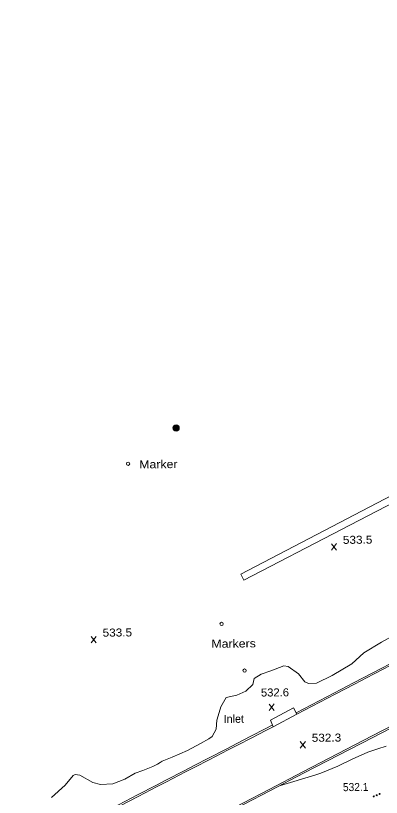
# Model space of a CAD drawing. Extents: x 2361284 to 2366480, y 6976556 to 6985346.
# Drawn here: x 2362327.9 to 2362547.3, y 6978202.6 to 6978671.2 of the extents above; entities that cross this region are included whole.
import ezdxf

# ---------------------------------------------------------------- set-up
doc = ezdxf.new("R2010")
doc.units = 0
doc.header["$LTSCALE"] = 1.9
for name, color, linetype, lineweight in [('12', 7, 'Continuous', 13), ('13', 7, 'Continuous', 13), ('21', 7, 'Continuous', 13), ('3', 7, 'Continuous', 13), ('4', 7, 'Continuous', 13), ('7', 7, 'Continuous', 13), ('8', 7, 'Continuous', 13)]:
    doc.layers.add(name, color=color, linetype=linetype, lineweight=lineweight)

msp = doc.modelspace()

# ---------------------------------------------------------------- linework, layer by layer
at = {"layer": '12'}
for p, q in [((2362520.443, 6978350.813), (2362517.326, 6978354.664)), ((2362517.363, 6978350.784), (2362520.406, 6978354.693)), ((2362376.315, 6978295.21), (2362373.198, 6978299.061)), ((2362373.235, 6978295.181), (2362376.278, 6978299.09)), ((2362483.024, 6978254.721), (2362479.907, 6978258.572)), ((2362479.944, 6978254.692), (2362482.987, 6978258.601)), ((2362501.75, 6978232.188), (2362498.633, 6978236.039)), ((2362498.67, 6978232.159), (2362501.713, 6978236.068))]:
    msp.add_line(p, q, dxfattribs=at)
at = {"layer": '13'}
for points in [[(2362606.115, 6978310.613), (2362602.962, 6978315.072), (2362600.891, 6978317.323), (2362599.072, 6978317.856), (2362595.125, 6978316.798), (2362585.879, 6978312.11), (2362580.474, 6978310.519), (2362568.627, 6978304.796), (2362556.059, 6978300.457), (2362547.294, 6978295.592), (2362536.815, 6978289.202), (2362529.547, 6978282.674), (2362517.762, 6978275.611), (2362508.376, 6978271.131), (2362503.665, 6978270.847), (2362501.428, 6978271.825), (2362497.551, 6978276.719), (2362491.32, 6978281.01)], [(2362491.32, 6978281.01), (2362488.805, 6978281.466), (2362481.064, 6978278.423), (2362475.303, 6978276.368), (2362470.937, 6978273.825), (2362470.151, 6978270.277), (2362465.908, 6978266.307), (2362460.671, 6978263.787), (2362454.283, 6978262.506), (2362451.028, 6978256.855), (2362450.531, 6978255.46), (2362448.674, 6978248.842), (2362448.255, 6978243.458), (2362445.722, 6978239.13), (2362443.76, 6978237.625), (2362438.794, 6978234.968), (2362430.964, 6978230.703), (2362421.833, 6978226.705), (2362415.755, 6978224.258)], [(2362550.136, 6978233.316), (2362545.21, 6978231.769), (2362539.25, 6978229.663), (2362529.831, 6978225.463), (2362521.169, 6978221.24), (2362511.088, 6978217.094), (2362507.351, 6978215.899), (2362486.807, 6978209.793)], [(2362415.755, 6978224.258), (2362414.542, 6978223.547), (2362412.942, 6978222.471), (2362410.174, 6978221.155), (2362404.136, 6978218.807), (2362399.702, 6978217.165), (2362393.435, 6978213.595), (2362386.182, 6978210.806), (2362378.866, 6978210.337), (2362374.135, 6978211.442), (2362366.501, 6978216.019), (2362363.638, 6978216.365), (2362362.343, 6978215.79), (2362357.738, 6978210.016), (2362349.417, 6978202.565)]]:
    msp.add_lwpolyline(points, dxfattribs=at)
at = {"layer": '21'}
for centre in [(2362546.243, 6978204.663), (2362542.717, 6978203.145), (2362544.486, 6978203.89)]:
    msp.add_circle(centre, 0.3, dxfattribs=at)
at = {"layer": '3'}
msp.add_line((2362482.302, 6978244.952), (2362496.631, 6978252.519), dxfattribs=at)
for points in [[(2362462.946, 6978336.358), (2362464.803, 6978332.781), (2362699.124, 6978454.268), (2362589.904, 6978664.638)], [(2362981.445, 6978467.35), (2362809.007, 6978377.835), (2362710.231, 6978326.575), (2362660.839, 6978300.953), (2362647.619, 6978294.102), (2362621.168, 6978280.42), (2362568.25, 6978253.087), (2362541.798, 6978239.407), (2362500.635, 6978218.082), (2362480.057, 6978207.412), (2362449.196, 6978191.397), (2362402.915, 6978167.353), (2362365.587, 6978147.925), (2362340.71, 6978134.956), (2362290.974, 6978108.986)], [(2362981.883, 6978466.494), (2362809.445, 6978376.979), (2362710.67, 6978325.719), (2362661.278, 6978300.097), (2362648.058, 6978293.246), (2362621.607, 6978279.564), (2362568.688, 6978252.231), (2362542.236, 6978238.551), (2362501.073, 6978217.226), (2362480.496, 6978206.556), (2362449.635, 6978190.541), (2362403.354, 6978166.498), (2362366.029, 6978147.073), (2362341.154, 6978134.106), (2362291.422, 6978108.14)], [(2362496.183, 6978253.375), (2362519.166, 6978265.37), (2362530.658, 6978271.366), (2362542.151, 6978277.359), (2362547.898, 6978280.355), (2362559.394, 6978286.344), (2362565.143, 6978289.337), (2362573.767, 6978293.825), (2362581.434, 6978297.812), (2362585.267, 6978299.805), (2362591.019, 6978302.793), (2362599.647, 6978307.272), (2362608.277, 6978311.748), (2362612.593, 6978313.984), (2362661.176, 6978339.151), (2362725.955, 6978372.706), (2362758.344, 6978389.485), (2362789.439, 6978405.594), (2362804.986, 6978413.649)], [(2362496.631, 6978252.519), (2362519.612, 6978264.514), (2362531.103, 6978270.509), (2362542.596, 6978276.503), (2362548.342, 6978279.499), (2362559.837, 6978285.488), (2362565.585, 6978288.481), (2362574.208, 6978292.969), (2362581.874, 6978296.956), (2362585.708, 6978298.949), (2362591.458, 6978301.937), (2362600.086, 6978306.416), (2362608.716, 6978310.892), (2362613.031, 6978313.128), (2362629.225, 6978321.518), (2362661.614, 6978338.296), (2362726.393, 6978371.85), (2362758.782, 6978388.629), (2362789.877, 6978404.739), (2362805.424, 6978412.794)], [(2362325.127, 6978164.622), (2362329.659, 6978166.981), (2362336.458, 6978170.519), (2362345.525, 6978175.235), (2362350.058, 6978177.591), (2362356.86, 6978181.125), (2362367.063, 6978186.423), (2362377.135, 6978191.649), (2362382.171, 6978194.261), (2362389.727, 6978198.179), (2362401.061, 6978204.052), (2362412.397, 6978209.922), (2362418.065, 6978212.856), (2362429.403, 6978218.722), (2362435.073, 6978221.653), (2362443.578, 6978226.049), (2362454.92, 6978231.908), (2362460.592, 6978234.836), (2362469.1, 6978239.226), (2362477.609, 6978243.614), (2362481.864, 6978245.808)], [(2362325.57, 6978163.766), (2362330.101, 6978166.126), (2362336.9, 6978169.664), (2362345.965, 6978174.379), (2362350.498, 6978176.736), (2362357.299, 6978180.27), (2362367.501, 6978185.568), (2362377.573, 6978190.795), (2362382.609, 6978193.407), (2362390.164, 6978197.324), (2362401.498, 6978203.198), (2362412.834, 6978209.068), (2362418.502, 6978212.002), (2362429.841, 6978217.867), (2362435.51, 6978220.799), (2362444.016, 6978225.194), (2362455.358, 6978231.052), (2362461.029, 6978233.98), (2362469.538, 6978238.37), (2362478.047, 6978242.759), (2362482.302, 6978244.952)]]:
    msp.add_lwpolyline(points, dxfattribs=at)
at = {"layer": '4'}
for centre, radius in [((2362424.197, 6978424.048), 1.9), ((2362424.197, 6978424.048), 1.442), ((2362424.197, 6978424.048), 0.539), ((2362424.197, 6978424.048), 0.192), ((2362395.411, 6978402.624), 1), ((2362451.468, 6978306.532), 1), ((2362465.245, 6978278.592), 1)]:
    msp.add_circle(centre, radius, dxfattribs=at)
for start, end in [(118.46406, 129.71409), (107.21593, 118.46597), (95.96582, 107.21585), (84.71553, 95.96557), (73.46552, 84.71555), (62.21535, 73.46538), (50.96397, 62.214), (174.71552, 185.96556), (163.46611, 174.71615), (185.96287, 197.21291), (152.21535, 163.46538), (197.21479, 208.46483), (140.96646, 152.21649), (208.46822, 219.71826), (129.71376, 140.96379), (219.71376, 230.96379), (230.96397, 242.214), (242.21812, 253.46815), (253.46258, 264.71261), (264.71553, 275.96557), (275.96582, 287.21585), (287.21593, 298.46597), (298.46406, 309.71409), (39.71588, 50.96591), (309.71589, 320.96592), (28.46656, 39.7166), (320.96646, 332.21649), (17.21479, 28.46483), (332.21419, 343.46422), (5.96345, 17.21348), (343.46611, 354.71615), (354.71553, 5.96557)]:
    msp.add_arc((2362424.197, 6978424.048), 0.973, start, end, dxfattribs=at)
at = {"layer": '7'}
msp.add_lwpolyline([(2362462.946, 6978336.358), (2362685.503, 6978452.391), (2362689.369, 6978464.208), (2362579.929, 6978674.474)], dxfattribs=at)
at = {"layer": '8'}
msp.add_lwpolyline([(2362496.631, 6978252.519), (2362494.576, 6978256.189), (2362480.715, 6978248.837), (2362482.302, 6978244.952)], dxfattribs=at)

# ---------------------------------------------------------------- texts
at = {"layer": '12'}
for s, width, p in [('533.5', 1.1, (2362524.252, 6978354.537)), ('533.5', 1.1, (2362380.123, 6978298.934)), ('532.6', 1.05, (2362475.07, 6978263.044)), ('532.3', 1.1, (2362505.559, 6978235.913)), ('532.1', 0.95, (2362524.271, 6978206.338))]:
    msp.add_text(s, height=4.799, rotation=0.545, dxfattribs=dict(at, width=width)).set_placement(p)
at = {"layer": '4', "width": 1.15}
for s, p in [('Marker', (2362402.086, 6978399.777)), ('Markers', (2362445.371, 6978292.283))]:
    msp.add_text(s, height=4.799, rotation=0.545, dxfattribs=at).set_placement(p)
at = {"layer": '8'}
msp.add_text('Inlet', height=4.799, rotation=0.545, dxfattribs=at).set_placement((2362452.759, 6978247.241))

doc.saveas('drawing.dxf')
